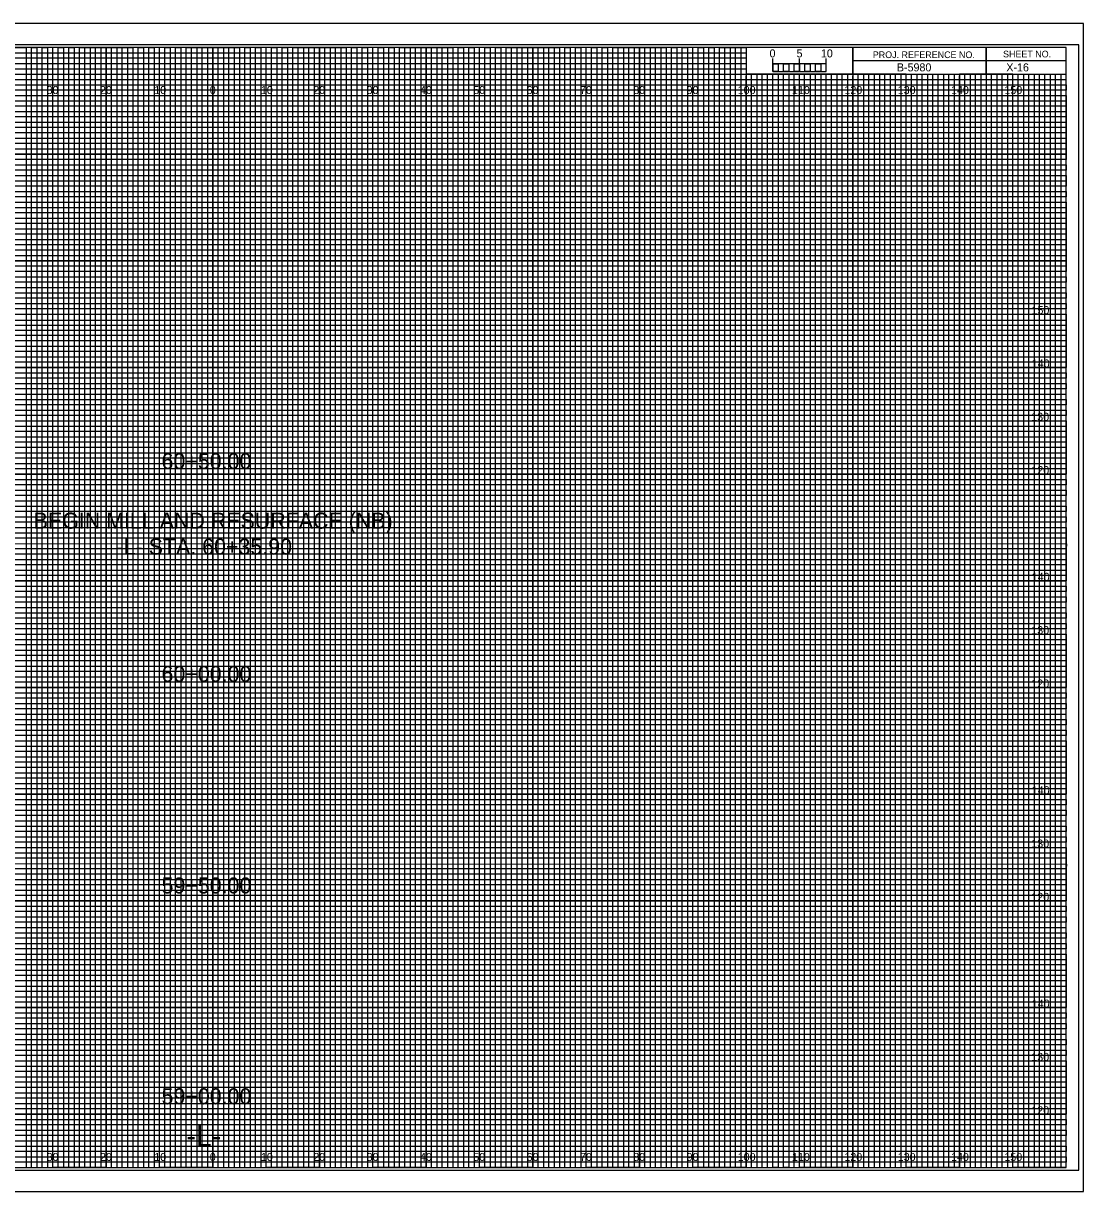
# Model space of a CAD drawing. Extents: x -13 to 323, y -5 to 1754.
# Drawn here: x 124.5 to 323.3, y -4.5 to 214.5 of the extents above; entities that cross this region are included whole.
import ezdxf

# ---------------------------------------------------------------- set-up
doc = ezdxf.new("R2010")
doc.units = 0
for name, color, linetype in [('Exist Cross Section Cell', 7, 'Continuous'), ('Exist XS Center Line Elevation Label', 7, 'Continuous'), ('Exist XS Ground Line', 7, 'Continuous'), ('Prop CMT Bridge Metal Rail', 7, 'Continuous'), ('Prop CMT Pvmt Course 1', 7, 'Continuous'), ('Prop CMT Pvmt Course 2', 7, 'Continuous'), ('Prop CMT Pvmt Course 3', 7, 'Continuous'), ('Prop CMT Pvmt Surface', 7, 'Continuous'), ('Prop CMT Pvmt Surface Shoulder', 7, 'Continuous'), ('Prop CMT Shld Paved Course 1', 7, 'Continuous'), ('Prop CMT Shld Paved Course 2', 7, 'Continuous'), ('Prop CMT Shld Paved Course 3', 7, 'Continuous'), ('Prop CMT Slope Grass', 7, 'Continuous'), ('Prop CMT Subgrade Earthwork', 7, 'Continuous'), ('Prop XS Shear Point Element', 7, 'Continuous'), ('Prop XS Shear Point Label', 7, 'Continuous'), ('Scratch_Level_1', 7, 'Continuous')]:
    doc.layers.add(name, color=color, linetype=linetype)

msp = doc.modelspace()

# ---------------------------------------------------------------- linework, layer by layer
at = {"layer": 'Exist XS Center Line Elevation Label'}
for points in [[(115, 210), (125, 210), (125, 0), (135, 0), (135, 210), (145, 210), (145, 0), (155, 0), (155, 210), (165, 210), (165, 0), (175, 0), (175, 210), (185, 210), (185, 0), (195, 0), (195, 210), (205, 210), (205, 0), (215, 0), (215, 210), (225, 210), (225, 0), (235, 0), (235, 210), (245, 210), (245, 0), (255, 0), (255, 210), (259.93, 210), (260, 210), (260, 205), (264.99, 205), (264.99, 0), (275, 0), (275, 205), (285, 205), (285, 0), (295, 0), (295, 205), (305, 205), (305, 0), (315, 0), (315, 205)], [(0, 205), (275, 205)], [(0, 185), (320, 185), (320, 195), (0, 195)], [(0, 165), (320, 165), (320, 175), (0, 175)], [(0, 145), (320, 145), (320, 155), (0, 155)], [(0, 125), (320, 125), (320, 135), (0, 135)], [(0, 105), (320, 105), (320, 115), (0, 115)], [(0, 85), (320, 85), (320, 95), (0, 95)], [(0, 65), (320, 65), (320, 75), (0, 75)], [(0, 45), (320, 45), (320, 55), (0, 55)], [(0, 25), (320, 25), (320, 35), (0, 35)], [(0, 5), (320, 5), (320, 15), (0, 15)]]:
    msp.add_lwpolyline(points, dxfattribs=at)
at = {"layer": 'Exist XS Ground Line'}
for p, q in [((130, 210), (120, 210)), ((130, 0), (130, 210)), ((150, 210), (140, 210)), ((140, 210), (140, 0)), ((150, 0), (150, 210)), ((170, 210), (160, 210)), ((160, 210), (160, 0)), ((170, 0), (170, 210)), ((190, 210), (180, 210)), ((180, 210), (180, 0)), ((190, 0), (190, 210)), ((210, 210), (200, 210)), ((200, 210), (200, 0)), ((210, 0), (210, 210)), ((230, 210), (220, 210)), ((220, 210), (220, 0)), ((230, 0), (230, 210)), ((250, 210), (240, 210)), ((240, 210), (240, 0)), ((250, 0), (250, 210)), ((260, 210), (260, 0)), ((270, 0), (270, 205)), ((290, 205), (280, 205)), ((280, 205), (280, 0)), ((290, 0), (290, 205)), ((310, 205), (300, 205)), ((300, 205), (300, 0)), ((310, 0), (310, 205)), ((140, 0), (130, 0)), ((160, 0), (150, 0)), ((180, 0), (170, 0)), ((200, 0), (190, 0)), ((220, 0), (210, 0)), ((240, 0), (230, 0)), ((260, 0), (250, 0)), ((280, 0), (270, 0)), ((300, 0), (290, 0)), ((320, 0), (310, 0)), ((320, 0), (320, 0))]:
    msp.add_line(p, q, dxfattribs=at)
for points in [[(0, 200), (320, 200), (320, 190), (0, 190)], [(0, 180), (320, 180), (320, 170), (0, 170)], [(0, 160), (320, 160), (320, 150), (0, 150)], [(0, 140), (320, 140), (320, 130), (0, 130)], [(0, 120), (320, 120), (320, 110), (0, 110)], [(0, 100), (320, 100), (320, 90), (0, 90)], [(0, 80), (320, 80), (320, 70), (0, 70)], [(0, 60), (320, 60), (320, 50), (0, 50)], [(0, 40), (320, 40), (320, 30), (0, 30)], [(0, 20), (320, 20), (320, 10), (0, 10)]]:
    msp.add_lwpolyline(points, dxfattribs=at)
at = {"layer": 'Prop CMT Pvmt Course 2'}
for p, q in [((265, 205.49), (265, 207.9)), ((265, 206.9), (265, 207.9)), ((270, 205.49), (270, 207.9)), ((275, 205.49), (275, 207.9)), ((275, 206.9), (275, 207.9))]:
    msp.add_line(p, q, dxfattribs=at)
for points in [[(275, 206.9), (265, 206.9), (265, 205.49), (275, 205.49)], [(265, 206.9), (266, 206.9), (266, 205.49), (265, 205.49)], [(267, 206.9), (268, 206.9), (268, 205.49), (267, 205.49)], [(269, 206.9), (270, 206.9), (270, 205.49), (269, 205.49)], [(271, 206.9), (272, 206.9), (272, 205.49), (271, 205.49)], [(273, 206.9), (274, 206.9), (274, 205.49), (273, 205.49)]]:
    msp.add_lwpolyline(points, close=True, dxfattribs=at)
at = {"layer": 'Prop CMT Pvmt Course 3'}
msp.add_lwpolyline([(-13.4, -4.5), (323.3, -4.5), (323.3, 214.5), (-13.4, 214.5)], close=True, dxfattribs=at)
at = {"layer": 'Prop CMT Pvmt Surface'}
for p, q in [((130, 0), (130, 210)), ((140, 0), (140, 210)), ((150, 0), (150, 210)), ((160, 0), (160, 210)), ((170, 0), (170, 210)), ((180, 0), (180, 210)), ((190, 0), (190, 210)), ((200, 0), (200, 210)), ((210, 0), (210, 210)), ((220, 0), (220, 210)), ((230, 0), (230, 210)), ((240, 0), (240, 210)), ((250, 0), (250, 210)), ((260, 0), (260, 204.69)), ((270, 0), (270, 204.69)), ((280, 0), (280, 204.69)), ((290, 0), (290, 204.69)), ((300, 0), (300, 204.69)), ((310, 0), (310, 204.69)), ((0, 200), (320, 200)), ((0, 190), (320, 190)), ((0, 180), (320, 180)), ((0, 170), (320, 170)), ((0, 160), (320, 160)), ((0, 150), (320, 150)), ((0, 140), (320, 140)), ((0, 130), (320, 130)), ((0, 120), (320, 120)), ((0, 110), (320, 110)), ((0, 100), (320, 100)), ((0, 90), (320, 90)), ((0, 80), (320, 80)), ((0, 70), (320, 70)), ((0, 60), (320, 60)), ((0, 50), (320, 50)), ((0, 40), (320, 40)), ((0, 30), (320, 30)), ((0, 20), (320, 20)), ((0, 10), (320, 10))]:
    msp.add_line(p, q, dxfattribs=at)
at = {"layer": 'Prop CMT Pvmt Surface Shoulder'}
for p, q in [((323.3, 214.5), (-13.4, 214.5)), ((-13.4, -4.5), (323.3, -4.5))]:
    msp.add_line(p, q, dxfattribs=at)
at = {"layer": 'Prop CMT Shld Paved Course 1'}
for p, q in [((0, 209), (260, 209)), ((260, 209), (260, 207.98)), ((260, 207.98), (0, 207.98)), ((0, 207), (260, 207)), ((260, 205.89), (0, 205.89)), ((260, 207), (260, 205.89)), ((0, 204), (320, 204))]:
    msp.add_line(p, q, dxfattribs=at)
for points in [[(0, 203), (270, 203), (320, 203), (320, 202), (0, 202)], [(0, 201), (320, 201), (320, 199), (0, 199)], [(0, 198), (320, 198), (320, 197), (0, 196.98)], [(0, 196), (320, 196), (320, 194), (0, 194)], [(0, 193), (320, 193), (320, 192), (0, 192)], [(0, 191), (320, 191), (320, 189), (0, 189)], [(0, 188), (320, 188), (320, 187), (0, 187)], [(0, 186), (320, 186), (320, 184), (0, 184)], [(0, 183), (320, 183), (320, 182), (0, 182)], [(0, 181), (320, 181), (320, 179), (0, 179)], [(0, 178), (320, 178), (320, 177), (0, 177)], [(0, 176), (320, 176), (320, 173.95), (320, 173), (320, 172), (0, 172)], [(0, 174), (320, 174), (320, 173), (0, 173)], [(0, 171), (320, 171), (320, 169), (0, 169.03)], [(0, 169.03), (320, 169), (320, 168), (0, 168)], [(0, 167), (320, 167), (320, 166), (0, 166)], [(0, 164), (320, 164), (320, 163), (0, 163)], [(0, 162), (320, 162), (320, 161), (0, 161)], [(-0.07, 158.89), (320, 158.89), (320, 157.88), (-0.07, 157.88)], [(0, 157), (320, 157), (320, 156), (0, 156)], [(0, 154), (320, 154), (320, 153), (0, 153)], [(0, 152), (320, 152), (320, 151), (0, 151)], [(0, 149), (320, 149), (320, 148), (0, 148)], [(0, 147), (320, 147), (320, 146), (0, 146)], [(0, 144), (320, 144), (320, 143), (0, 143)], [(0, 142), (320, 142), (320, 141), (0, 141)], [(0, 139), (320, 139), (319.99, 137.98), (0, 138)], [(0, 137), (320, 137), (320, 136), (0, 136)], [(0, 134), (320, 134), (320, 133), (0, 133)], [(0, 132), (320, 132), (320, 131), (0, 131)], [(0, 129), (320, 129), (320, 128), (0, 128)], [(0, 127), (320, 127), (320, 126), (0, 126)], [(0, 124), (320, 124), (320, 123), (0, 123)], [(0, 122), (320, 122), (320, 121), (0, 121)], [(0, 119), (320, 119), (320, 118), (0, 118)], [(0, 116.99), (320.07, 116.91), (320, 116), (0, 116)], [(0, 114), (320, 114), (320, 113), (0, 113)], [(0, 112), (320, 112), (320, 111), (0, 111)], [(0, 109), (320, 109), (320, 108), (0, 108)], [(0, 107), (320, 107), (320, 106), (0, 106)], [(0, 104), (320, 104), (320, 103), (0, 103)], [(0, 102), (320, 102), (320, 101), (0, 101)], [(0, 99), (320, 99), (320, 98), (0, 98)], [(0, 97), (320, 97), (320, 96), (0, 96)], [(0, 94), (320, 94), (320, 93), (0, 93)], [(0, 92), (320, 92), (320, 91), (0, 91)], [(0, 89), (320, 89), (320, 88), (0, 88)], [(0, 87), (320, 87), (320, 86), (0, 86)], [(0, 84), (320, 84), (320, 83), (0, 83)], [(0, 82), (320, 82), (320, 81), (0, 81)], [(0, 79), (320, 79), (319.99, 77.98), (0, 78)], [(0, 77), (320, 77), (320, 76), (0, 76)], [(0, 74), (320, 74), (320, 73), (0, 73)], [(0, 72), (320, 72), (320, 71), (0, 71)], [(0, 69), (320, 69), (320, 68), (0, 68)], [(0, 67), (320, 67), (320, 66), (0, 66)], [(0, 64), (320, 64), (320, 63), (0, 63)], [(0, 62), (320, 62), (320, 61), (0, 61)], [(0, 59), (320, 59), (320, 58), (0, 58)], [(0, 56.99), (320.07, 56.91), (320, 56), (0, 56)], [(0, 54), (320, 54), (320, 53), (0, 53)], [(0, 52), (320, 52), (320, 51), (0, 51)], [(0, 49), (320, 49), (320, 48), (0, 48)], [(0, 47), (320, 47), (320, 46), (0, 46)], [(0, 44), (320, 44), (320, 43), (0, 43)], [(0, 42), (320, 42), (320, 41), (0, 41)], [(0, 39), (320, 39), (320, 38), (0, 38)], [(0, 37), (320, 37), (320, 36), (0, 36)], [(0, 34), (320, 34), (320, 33), (0, 33)], [(0, 32), (320, 32), (320, 31), (0, 31)], [(0, 29), (320, 29), (320, 28), (0, 28)], [(0, 27), (320, 27), (320, 26), (0, 26)], [(0, 24), (320, 24), (320, 23), (0, 23)], [(0, 22), (320, 22), (320, 21), (0, 21)], [(0, 19), (320, 19), (320, 18), (0, 18)], [(0, 17), (320, 17), (320, 16), (0, 16)], [(0, 14), (320, 14), (320, 13), (0, 13)], [(0, 12), (320, 12), (320, 11), (0, 11)], [(0, 9), (320, 9), (320, 8), (0, 8)], [(0, 7), (320, 7), (320, 6), (0, 6)], [(0, 4), (320, 4), (320, 3), (0, 3)], [(0, 2), (320, 2), (320, 1), (0, 1)]]:
    msp.add_lwpolyline(points, dxfattribs=at)
at = {"layer": 'Prop CMT Shld Paved Course 2'}
for p, q in [((305, 210), (305, 205)), ((305, 205), (305, 210)), ((280, 207.5), (280, 205)), ((320, 207.49), (280, 207.49)), ((280, 205), (320, 205))]:
    msp.add_line(p, q, dxfattribs=at)
for points in [[(320, 210), (0, 210), (0, 0), (320, 0)], [(280, 210), (260, 210), (260, 205.03), (280, 205.03)], [(320, 210), (280, 210), (280, 205), (320, 205)]]:
    msp.add_lwpolyline(points, close=True, dxfattribs=at)
at = {"layer": 'Prop CMT Shld Paved Course 3'}
for p, q in [((267, 205), (266.01, 205)), ((266.01, 205), (266.01, 0)), ((267, 0), (267, 205)), ((269, 205), (268, 205)), ((268, 205), (268, 0)), ((269, 0), (269, 205)), ((266.01, 0), (265, 0)), ((268, 0), (267, 0))]:
    msp.add_line(p, q, dxfattribs=at)
for points in [[(125, 0), (126, 0), (126, 210), (127, 210), (127, 0)], [(127, 0), (128, 0), (128, 210), (129, 210), (129, 0)], [(130, 0), (131, 0), (131, 210), (132, 210), (132, 0)], [(132, 0), (133, 0), (133, 210), (134, 210), (134, 0)], [(135, 0), (136, 0), (136, 210), (137, 210), (137, 0)], [(137, 0), (138, 0), (138, 210), (139, 210), (139, 0)], [(140, 0), (141, 0), (141, 210), (142, 210), (142, 0)], [(142, 0), (143, 0), (143, 210), (144, 210), (144, 0)], [(145, 0), (146, 0), (146, 210), (147, 210), (147, 0)], [(147, 0), (148, 0), (148, 210), (149, 210), (149, 0)], [(150, 0), (151, 0), (151, 210), (152, 210), (152, 0)], [(152, 0), (153, 0), (153, 210), (154, 210), (154, 0)], [(155, 0), (156, 0), (156, 210), (157, 210), (157, 0)], [(157, 0), (158, 0), (158, 210), (159, 210), (159, 0)], [(160, 0), (161, 0), (161, 210), (162, 210), (162, 0)], [(162, 0), (163, 0), (163, 210), (164, 210), (164, 0)], [(165, 0), (166, 0), (166, 210), (167, 210), (167, 0)], [(167, 0), (168, 0), (168, 210), (169, 210), (169, 0)], [(170, 0), (171, 0), (171, 210), (172, 210), (172, 0)], [(172, 0), (173, 0), (173, 210), (174, 210), (174, 0)], [(175, 0), (176, 0), (176, 210), (177, 210), (177, 0)], [(177, 0), (178, 0), (178, 210), (179, 210), (179, 0)], [(180, 0), (181, 0), (181, 210), (182, 210), (182, 0)], [(182, 0), (183, 0), (183, 210), (184, 210), (184, 0)], [(185, 0), (186, 0), (186, 210), (187, 210), (187, 0)], [(187, 0), (188, 0), (188, 210), (189, 210), (189, 0)], [(190, 0), (191, 0), (191, 210), (192, 210), (192, 0)], [(192, 0), (193, 0), (193, 210), (194, 210), (194, 0)], [(195, 0), (196, 0), (196, 210), (197, 210), (197, 0)], [(197, 0), (198, 0), (198, 210), (199, 210), (199, 0)], [(200, 0), (201, 0), (201, 210), (202, 210), (202, 0)], [(202, 0), (203, 0), (203, 210), (204, 210), (204, 0)], [(205, 0), (206, 0), (206, 210), (207, 210), (207, 0)], [(207, 0), (208, 0), (208, 210), (209, 210), (209, 0)], [(210, 0), (211, 0), (211, 210), (212, 210), (212, 0)], [(212, 0), (213, 0), (213, 210), (214, 210), (214, 0)], [(215, 0), (216, 0), (216, 210), (217, 210), (217, 0)], [(217, 0), (218, 0), (218, 210), (219, 210), (219, 0)], [(220, 0), (221, 0), (221, 210), (222, 210), (222, 0)], [(222, 0), (223, 0), (223, 210), (224, 210), (224, 0)], [(225, 0), (226, 0), (226, 210), (227, 210), (227, 0)], [(227, 0), (228, 0), (228, 210), (229, 210), (229, 0)], [(230, 0), (231, 0), (231, 210), (232, 210), (232, 0)], [(232, 0), (233, 0), (233, 210), (234, 210), (234, 0)], [(235, 0), (236, 0), (236, 210), (237, 210), (237, 0)], [(237, 0), (238, 0), (238, 210), (239, 210), (239, 0)], [(240, 0), (241, 0), (241, 210), (242, 210), (242, 0)], [(242, 0), (243, 0), (243, 210), (244, 210), (244, 0)], [(245, 0), (246, 0), (246, 210), (247, 210), (247, 0)], [(247, 0), (248, 0), (248, 210), (249, 210), (249, 0)], [(250, 0), (251, 0), (251, 210), (252, 210), (252, 0)], [(252, 0), (253, 0), (253, 210), (254, 210), (254, 0)], [(255, 0), (256, 0), (256, 210), (257, 210), (257, 0)], [(257, 0), (258, 0), (258, 210), (259, 210), (259, 0)], [(260, 0), (261, 0), (261, 205), (262.02, 205), (262.02, 0)], [(262, 0), (263, 0), (263, 205), (263.99, 205), (263.99, 0)], [(270, 0), (270.98, 0), (270.98, 205), (272, 205), (272, 0)], [(272, 0), (273, 0), (273, 205), (274.05, 205), (274.05, 0)], [(275, 0), (276, 0), (276, 205), (277, 205), (277, 0)], [(277, 0), (278, 0), (278, 205), (279, 205), (279, 0)], [(280, 0), (281, 0), (281, 205), (282, 205), (282, 0)], [(282, 0), (283, 0), (283, 205), (284, 205), (284, 0)], [(285, 0), (286, 0), (286, 205), (287, 205), (287, 0)], [(287, 0), (288, 0), (288, 205), (289, 205), (289, 0)], [(290, 0), (291, 0), (291, 205), (292, 205), (292, 0)], [(292, 0), (293, 0), (293, 205), (294, 205), (294, 0)], [(295, 0), (296, 0), (296, 205), (297, 205), (297, 0)], [(297, 0), (298, 0), (298, 205), (299, 205), (299, 0)], [(300, 0), (301, 0), (301, 205), (302, 205), (302, 0)], [(302, 0), (303, 0), (303, 205), (304, 205), (304, 0)], [(305, 0), (306, 0), (306, 205), (307, 205), (307, 0)], [(307, 0), (308, 0), (308, 205), (309, 205), (309, 0)], [(310, 0), (311, 0), (311, 205), (312, 205), (312, 0)], [(312, 0), (313, 0), (313, 205), (314, 205), (314, 0)], [(315, 0), (316, 0), (316, 205), (317, 205), (317, 0)], [(317, 0), (318, 0), (318, 205), (319, 205), (319, 0)]]:
    msp.add_lwpolyline(points, dxfattribs=at)
at = {"layer": 'Prop CMT Subgrade Earthwork'}
msp.add_lwpolyline([(-10.8, -0.5), (322.4, -0.5), (322.4, 210.5), (-10.8, 210.5)], close=True, dxfattribs=at)

# ---------------------------------------------------------------- texts
at = {"layer": 'Exist Cross Section Cell'}
for s, p in [('30', (128.86, 201.25)), ('20', (138.86, 201.25)), ('10', (149.04, 201.25)), ('0', (159.45, 201.25)), ('0', (159.45, 201.25)), ('10', (169.04, 201.25)), ('20', (178.86, 201.25)), ('30', (188.86, 201.25)), ('40', (198.86, 201.25)), ('50', (208.86, 201.25)), ('60', (218.86, 201.25)), ('70', (228.86, 201.25)), ('80', (238.86, 201.25)), ('90', (248.86, 201.25)), ('100', (258.44, 201.25)), ('110', (268.62, 201.25)), ('120', (278.44, 201.25)), ('130', (288.44, 201.25)), ('140', (298.44, 201.25)), ('150', (308.44, 201.25)), ('30', (128.86, 1.25)), ('20', (138.86, 1.25)), ('10', (149.04, 1.25)), ('0', (159.45, 1.25)), ('0', (159.45, 1.25)), ('10', (169.04, 1.25)), ('20', (178.86, 1.25)), ('30', (188.86, 1.25)), ('40', (198.86, 1.25)), ('50', (208.86, 1.25)), ('60', (218.86, 1.25)), ('70', (228.86, 1.25)), ('80', (238.86, 1.25)), ('90', (248.86, 1.25)), ('100', (258.44, 1.25)), ('110', (268.62, 1.25)), ('120', (278.44, 1.25)), ('130', (288.44, 1.25)), ('140', (298.44, 1.25)), ('150', (308.44, 1.25))]:
    msp.add_text(s, height=1.5, dxfattribs=at).set_placement(p)
at = {"layer": 'Prop CMT Bridge Metal Rail'}
for s, p in [('5', (269.47, 208.12)), ('10', (274.04, 208.12))]:
    msp.add_text(s, height=1.5, dxfattribs=at).set_placement(p)
at = {"layer": 'Prop CMT Pvmt Course 1'}
for s, p in [('150', (313.52, 160)), ('140', (313.57, 150)), ('130', (313.49, 140)), ('120', (313.5, 130)), ('140', (313.57, 110)), ('130', (313.49, 100)), ('120', (313.5, 90)), ('140', (313.57, 70)), ('130', (313.49, 60)), ('120', (313.5, 50)), ('140', (313.57, 30)), ('130', (313.49, 20)), ('120', (313.5, 10))]:
    msp.add_text(s, height=1.5, dxfattribs=at).set_placement(p)
at = {"layer": 'Prop CMT Pvmt Course 2'}
msp.add_text('0', height=1.5, dxfattribs=at).set_placement((264.41, 208.12))
at = {"layer": 'Prop CMT Shld Paved Course 2'}
for s, p in [('PROJ. REFERENCE NO.', (283.77, 207.99)), ('SHEET NO.', (308.19, 208.12))]:
    msp.add_text(s, height=1.25, dxfattribs=at).set_placement(p)
at = {"layer": 'Prop CMT Slope Grass'}
for s, p in [('60+50.00', (150.41, 130.94)), ('BEGIN MILL AND RESURFACE (NB)', (126.43, 119.78)), ('-L- STA. 60+35.90', (141.98, 114.91)), ('60+00.00', (150.41, 91.04)), ('59+50.00', (150.41, 51.4)), ('59+00.00', (150.41, 11.87))]:
    msp.add_text(s, height=3, dxfattribs=at).set_placement(p)
at = {"layer": 'Prop XS Shear Point Element'}
msp.add_text('-L-', height=4, dxfattribs=at).set_placement((155.06, 4))
at = {"layer": 'Prop XS Shear Point Label'}
msp.add_text('B-5980', height=1.5, dxfattribs=at).set_placement((288.28, 205.5))
at = {"layer": 'Scratch_Level_1'}
msp.add_text('X-16', height=1.5, dxfattribs=at).set_placement((308.8, 205.5))

doc.saveas('drawing.dxf')
